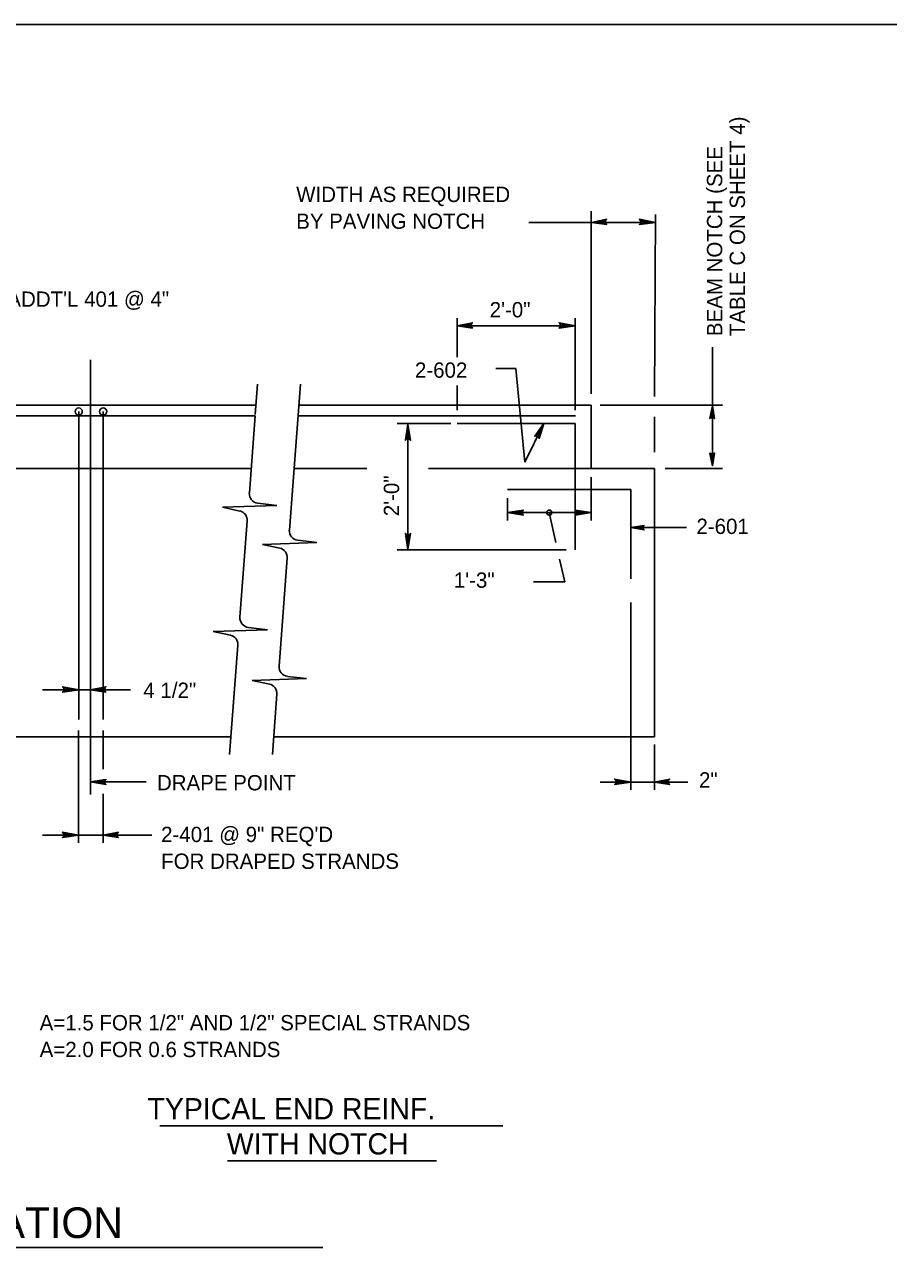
# Model space of a CAD drawing. Extents: x 637933 to 640019, y 298854 to 300042.
# Drawn here: x 638253.5 to 638422.7, y 299193.5 to 299433.1 of the extents above; entities that cross this region are included whole.
import ezdxf

# ---------------------------------------------------------------- set-up
doc = ezdxf.new("R2010")
doc.units = 0
doc.layers.add('1', color=7, linetype='Continuous')

msp = doc.modelspace()

# ---------------------------------------------------------------- linework, layer by layer
at = {"layer": '1'}
for p, q in [((638023.93, 299433.12), (638809.94, 299433.12)), ((638364.45, 299360.73), (638364.45, 299396.51)), ((638364.49, 299394.35), (638352.23, 299394.35)), ((638377.03, 299394.35), (638364.49, 299394.35)), ((638376.82, 299360.22), (638377.03, 299395.91)), ((638338.19, 299367.96), (638338.19, 299375.58)), ((638361.32, 299357.54), (638361.32, 299375.58)), ((638361.32, 299374.08), (638338.19, 299374.08)), ((638388.19, 299358.4), (638388.19, 299369.9)), ((638266.41, 299367.39), (638266.41, 299282.26)), ((638349.71, 299365.73), (638345.75, 299365.73)), ((638351.45, 299347.39), (638349.71, 299365.73)), ((638299.11, 299362.65), (638298.66, 299356.71)), ((638307.49, 299362.65), (638305.33, 299334.06)), ((638338.19, 299357.54), (638338.19, 299362.41)), ((638298.76, 299358.53), (638072.53, 299358.53)), ((638364.44, 299358.53), (638307.32, 299358.53)), ((638364.44, 299346.15), (638364.44, 299358.53)), ((638390.19, 299358.53), (638366.19, 299358.53)), ((638388.19, 299346.65), (638388.19, 299358.4)), ((638104.78, 299356.43), (638298.64, 299356.43)), ((638264.08, 299357.28), (638264.08, 299296.94)), ((638264.08, 299357.28), (638264.08, 299357.28)), ((638264.08, 299357.28), (638264.08, 299357.28)), ((638264.08, 299357.28), (638264.08, 299357.28)), ((638264.08, 299357.28), (638264.08, 299357.28)), ((638268.87, 299357.28), (638268.87, 299296.94)), ((638268.87, 299357.28), (638268.87, 299357.28)), ((638268.87, 299357.28), (638268.87, 299357.28)), ((638268.87, 299357.28), (638268.87, 299357.28)), ((638268.87, 299357.28), (638268.87, 299357.28)), ((638298.63, 299356.43), (638297.5, 299341.33)), ((638307.02, 299356.43), (638361.4, 299356.43)), ((638376.82, 299349.34), (638376.82, 299356.27)), ((638336.94, 299354.91), (638326.47, 299354.91)), ((638328.57, 299330.28), (638328.57, 299354.78)), ((638361.32, 299354.91), (638338.19, 299354.91)), ((638355.16, 299354.91), (638351.45, 299347.39)), ((638361.32, 299330.16), (638361.32, 299354.91)), ((638297.73, 299346.15), (638072.53, 299346.15)), ((638320.48, 299346.15), (638306.29, 299346.15)), ((638376.82, 299346.15), (638332.58, 299346.15)), ((638376.82, 299346.15), (638364.44, 299346.15)), ((638376.82, 299293.53), (638376.82, 299346.15)), ((638390.19, 299346.15), (638378.94, 299346.15)), ((638364.44, 299335.93), (638364.44, 299344.41)), ((638372.19, 299342.03), (638348.03, 299342.03)), ((638372.19, 299324.53), (638372.19, 299342.03)), ((638302.87, 299338.87), (638292.26, 299338.53)), ((638299.14, 299339.32), (638302.87, 299338.87)), ((638348.03, 299335.93), (638348.03, 299340.29)), ((638292.26, 299338.53), (638295.61, 299337.79)), ((638348.03, 299337.48), (638364.44, 299337.48)), ((638357.53, 299331.65), (638356.24, 299337.48)), ((638297.08, 299335.82), (638295.66, 299316.98)), ((638383.1, 299334.59), (638372.19, 299334.59)), ((638306.97, 299332.06), (638310.7, 299331.6)), ((638310.7, 299331.6), (638300.1, 299331.26)), ((638300.1, 299331.26), (638303.45, 299330.53)), ((638359.57, 299330.16), (638326.44, 299330.16)), ((638304.91, 299328.55), (638303.32, 299307.41)), ((638359.26, 299323.91), (638358.26, 299328.37)), ((638353.15, 299323.91), (638359.26, 299323.91)), ((638372.19, 299319.87), (638372.19, 299283.18)), ((638297.3, 299314.98), (638301.03, 299314.53)), ((638301.03, 299314.53), (638290.43, 299314.18)), ((638290.43, 299314.18), (638293.78, 299313.45)), ((638295.24, 299311.48), (638293.63, 299290.11)), ((638376.82, 299293.53), (638376.82, 299308.55)), ((638304.96, 299305.4), (638308.69, 299304.95)), ((638308.69, 299304.95), (638298.08, 299304.61)), ((638298.08, 299304.61), (638301.43, 299303.87)), ((638274.19, 299302.76), (638257.02, 299302.76)), ((638302.9, 299301.9), (638302.01, 299290.11)), ((638293.89, 299293.53), (638072.53, 299293.53)), ((638264.04, 299272.75), (638264.04, 299294.8)), ((638268.84, 299294.8), (638268.84, 299287.18)), ((638376.82, 299293.53), (638302.27, 299293.53)), ((638376.82, 299292.03), (638376.82, 299283.18)), ((638266.41, 299284.7), (638277.3, 299284.7)), ((638383.4, 299284.68), (638366.19, 299284.68)), ((638268.84, 299282.38), (638268.84, 299272.75)), ((638257.02, 299274.25), (638278.43, 299274.25)), ((638264.04, 299273.21), (638264.04, 299274.25)), ((638347.17, 299217.34), (638279.98, 299217.34)), ((638334.15, 299210.47), (638293.21, 299210.47)), ((638311.88, 299193.49), (638140.49, 299193.49))]:
    msp.add_line(p, q, dxfattribs=at)
for points in [[(638367.34, 299394.05), (638367.19, 299394.2), (638364.49, 299394.35), (638367.34, 299394.05), (638367.49, 299393.9), (638364.49, 299394.35), (638367.19, 299394.5), (638367.34, 299394.8), (638364.49, 299394.35), (638367.49, 299394.95), (638367.34, 299394.8)], [(638374.03, 299394.8), (638374.18, 299394.5), (638377.03, 299394.35), (638374.03, 299394.8), (638373.88, 299394.95), (638377.03, 299394.35), (638374.18, 299394.2), (638374.03, 299394.05), (638377.03, 299394.35), (638373.88, 299393.9), (638374.03, 299394.05)], [(638341.04, 299373.78), (638340.89, 299373.93), (638338.19, 299374.08), (638341.04, 299373.78), (638341.19, 299373.63), (638338.19, 299374.08), (638340.89, 299374.23), (638341.04, 299374.53), (638338.19, 299374.08), (638341.19, 299374.68), (638341.04, 299374.53)], [(638358.32, 299374.53), (638358.47, 299374.23), (638361.32, 299374.08), (638358.32, 299374.53), (638358.17, 299374.68), (638361.32, 299374.08), (638358.47, 299373.93), (638358.32, 299373.78), (638361.32, 299374.08), (638358.17, 299373.63), (638358.32, 299373.78)], [(638387.82, 299356.03), (638388.07, 299356.03), (638388.19, 299358.4), (638387.82, 299356.03), (638387.69, 299355.9), (638388.19, 299358.4), (638388.32, 299356.03), (638388.44, 299356.03), (638388.19, 299358.4), (638388.57, 299355.9), (638388.44, 299356.03)], [(638328.19, 299351.78), (638328.32, 299351.91), (638328.57, 299354.78), (638328.19, 299351.78), (638328.07, 299351.66), (638328.57, 299354.78), (638328.69, 299351.91), (638328.94, 299351.78), (638328.57, 299354.78), (638329.07, 299351.66), (638328.94, 299351.78)], [(638353.57, 299352.51), (638353.81, 299352.51), (638355.16, 299354.91), (638353.57, 299352.51), (638353.4, 299352.43), (638355.16, 299354.91), (638354.07, 299352.39), (638354.2, 299352.2), (638355.16, 299354.91), (638354.26, 299352.01), (638354.2, 299352.2)], [(638388.44, 299349.03), (638388.32, 299348.9), (638388.19, 299346.65), (638388.44, 299349.03), (638388.57, 299349.15), (638388.19, 299346.65), (638388.07, 299348.9), (638387.82, 299349.03), (638388.19, 299346.65), (638387.69, 299349.15), (638387.82, 299349.03)], [(638351.03, 299337.1), (638350.91, 299337.35), (638348.03, 299337.48), (638351.03, 299337.1), (638351.16, 299336.98), (638348.03, 299337.48), (638350.91, 299337.6), (638351.03, 299337.85), (638348.03, 299337.48), (638351.16, 299337.98), (638351.03, 299337.85)], [(638361.44, 299337.85), (638361.57, 299337.6), (638364.44, 299337.48), (638361.44, 299337.85), (638361.32, 299337.98), (638364.44, 299337.48), (638361.57, 299337.35), (638361.44, 299337.1), (638364.44, 299337.48), (638361.32, 299336.98), (638361.44, 299337.1)], [(638374.69, 299334.22), (638374.57, 299334.47), (638372.19, 299334.59), (638374.69, 299334.22), (638374.82, 299334.09), (638372.19, 299334.59), (638374.57, 299334.72), (638374.69, 299334.84), (638372.19, 299334.59), (638374.82, 299334.97), (638374.69, 299334.84)], [(638328.94, 299333.28), (638328.69, 299333.16), (638328.57, 299330.28), (638328.94, 299333.28), (638329.07, 299333.41), (638328.57, 299330.28), (638328.44, 299333.16), (638328.19, 299333.28), (638328.57, 299330.28), (638328.07, 299333.41), (638328.19, 299333.28)], [(638261.08, 299303.21), (638261.23, 299302.91), (638264.08, 299302.76), (638261.08, 299303.21), (638260.93, 299303.36), (638264.08, 299302.76), (638261.23, 299302.61), (638261.08, 299302.46), (638264.08, 299302.76), (638260.93, 299302.31), (638261.08, 299302.46)], [(638269.26, 299302.46), (638269.11, 299302.61), (638266.41, 299302.76), (638269.26, 299302.46), (638269.41, 299302.31), (638266.41, 299302.76), (638269.11, 299302.91), (638269.26, 299303.21), (638266.41, 299302.76), (638269.41, 299303.36), (638269.26, 299303.21)], [(638269.27, 299284.34), (638269.16, 299284.54), (638266.41, 299284.7), (638269.27, 299284.34), (638269.41, 299284.21), (638266.41, 299284.7), (638269.16, 299284.83), (638269.26, 299285.04), (638266.41, 299284.7), (638269.41, 299285.17), (638269.26, 299285.04)], [(638369.19, 299285.13), (638369.34, 299284.83), (638372.19, 299284.68), (638369.19, 299285.13), (638369.04, 299285.28), (638372.19, 299284.68), (638369.34, 299284.53), (638369.19, 299284.38), (638372.19, 299284.68), (638369.04, 299284.23), (638369.19, 299284.38)], [(638379.67, 299284.38), (638379.52, 299284.53), (638376.82, 299284.68), (638379.67, 299284.38), (638379.82, 299284.23), (638376.82, 299284.68), (638379.52, 299284.83), (638379.67, 299285.13), (638376.82, 299284.68), (638379.82, 299285.28), (638379.67, 299285.13)], [(638261.04, 299274.7), (638261.19, 299274.4), (638264.04, 299274.25), (638261.04, 299274.7), (638260.89, 299274.85), (638264.04, 299274.25), (638261.19, 299274.1), (638261.04, 299273.95), (638264.04, 299274.25), (638260.89, 299273.8), (638261.04, 299273.95)], [(638271.69, 299273.95), (638271.54, 299274.1), (638268.84, 299274.25), (638271.69, 299273.95), (638271.84, 299273.8), (638268.84, 299274.25), (638271.54, 299274.4), (638271.69, 299274.7), (638268.84, 299274.25), (638271.84, 299274.85), (638271.69, 299274.7)]]:
    msp.add_lwpolyline(points, dxfattribs=at)
for centre, radius in [((638264.08, 299357.28), 0.7), ((638268.87, 299357.28), 0.7), ((638356.24, 299337.48), 0.495)]:
    msp.add_circle(centre, radius, dxfattribs=at)
for centre, start, end in [((638299.37, 299341.18), 175.7051, 263.0749), ((638295.21, 299335.96), 355.6965, 77.6495), ((638307.2, 299333.92), 175.7051, 263.0749), ((638303.04, 299328.7), 355.6965, 77.6495), ((638297.53, 299316.84), 175.7051, 263.0749), ((638293.38, 299311.62), 355.6965, 77.6495), ((638305.19, 299307.27), 175.7051, 263.0749), ((638301.03, 299302.04), 355.6965, 77.6495)]:
    msp.add_arc(centre, 1.88, start, end, dxfattribs=at)

# ---------------------------------------------------------------- texts
for s, p in [('TABLE C ON SHEET 4)', (638394.57, 299372.06)), ('BEAM NOTCH (SEE', (638390.12, 299372.06)), ('2\'-0"', (638326.83, 299336.77))]:
    msp.add_text(s, height=3, rotation=90, dxfattribs=at).set_placement(p)
for s, height, p in [('WIDTH AS REQUIRED', 3, (638306.67, 299398.33)), ('BY PAVING NOTCH', 3, (638306.67, 299393.08)), ('4 ADDT\'L 401 @ 4"', 3, (638246.76, 299377.8)), ('2\'-0"', 3, (638344.57, 299375.73)), ('2-602', 3, (638329.93, 299363.9)), ('2-601', 3, (638385.06, 299333.29)), ('1\'-3"', 3, (638337.54, 299322.75)), ('4 1/2"', 3, (638276.74, 299301.17)), ('2"', 3, (638385.57, 299283.61)), ('DRAPE POINT', 3, (638279.4, 299283.06)), ('2-401 @ 9" REQ\'D', 3, (638280.22, 299272.93)), ('FOR DRAPED STRANDS', 3, (638280.22, 299267.68)), ('A=1.5 FOR 1/2" AND 1/2" SPECIAL STRANDS', 3, (638256.43, 299236.04)), ('A=2.0 FOR 0.6 STRANDS', 3, (638256.43, 299230.79)), ('TYPICAL END REINF.', 4.1665, (638277.55, 299218.59)), ('WITH NOTCH', 4.167, (638293.09, 299211.72)), ('PA BULB-TEE BEAM - ELEVATION', 6, (638143.43, 299195.35))]:
    msp.add_text(s, height=height, dxfattribs=at).set_placement(p)

doc.saveas('drawing.dxf')
